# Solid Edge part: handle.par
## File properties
Title: Handle
Author: Deepak Maini
Template: Normal.par
Last saved by: CADCIM
Revision: 5
Application: Solid Edge
Material: aluminum
Accuracy: 0.99
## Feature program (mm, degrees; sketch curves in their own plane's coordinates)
sketch for "unnamed RevolvedProtrusion 1" plane through (0, 0, 0) normal (0, -1, 0) x-axis (1, 0, 0)
  line (-87.868, 0) -> (-87.868, -4)
  line (-87.868, -4) -> (-79.868, -4)
  line (-79.868, -4) -> (-79.868, -5)
  line (-79.868, -5) -> (76.132, -5)
  line (76.132, -5) -> (76.132, -4)
  line (76.132, -4) -> (84.132, -4)
  line (84.132, -4) -> (84.132, 0)
  dimension (linear) = 84.132
revolve "unnamed RevolvedProtrusion 1" add full turn 360 deg about sketch line (-87.868, 0) -> (84.132, 0)
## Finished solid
Body 1: solid body, 7 faces, 6 edges, 0 vertices.
  Faces by surface: plane 4, cylinder 3
  Edges by curve: circle 6
Bounding box of the edges (mm): 172.000 x 10.000 x 10.000, from (-87.868, -5, -5) to (84.132, 5, 5).
Cylindrical faces by radius (mm): R4 x2, R5 x1
Planar faces by outward normal: +x 2, -x 2
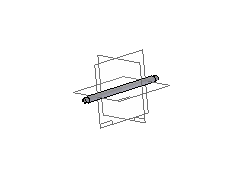
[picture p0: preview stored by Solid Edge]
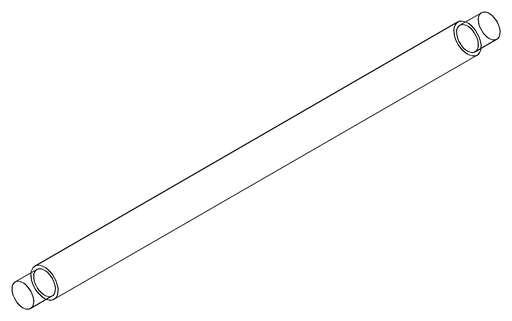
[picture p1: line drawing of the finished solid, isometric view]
